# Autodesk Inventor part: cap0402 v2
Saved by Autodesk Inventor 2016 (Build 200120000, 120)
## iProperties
Created: 2016-09
Part Number: cap0402 v2
Material: Generic
Document SubType Name: Modeling
Designer: Administrator
Appearance: Generic
Author: Administrator
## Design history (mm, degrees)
feature "Body6"
feature "Body8"
feature "Body18"
body "Solid1"
body "Solid2"
body "Solid3"
